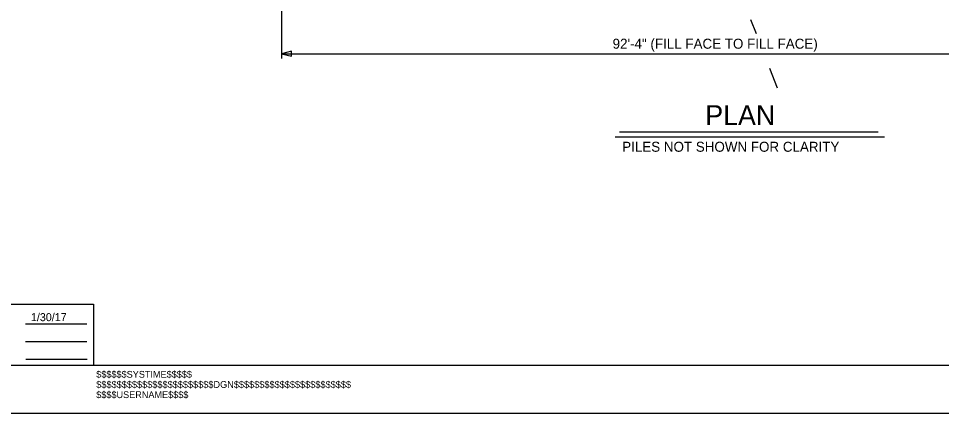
# Model space of a CAD drawing. Extents: x -20 to 509, y -659 to 21.
# Drawn here: x 47.1 to 139.4, y -176.3 to -136.8 of the extents above; entities that cross this region are included whole.
import ezdxf

# ---------------------------------------------------------------- set-up
doc = ezdxf.new("R2010")
doc.units = 0
for name, color, linetype in [('Auto Dimensioning', 7, 'Continuous'), ('Exist Hydro Stream or Body of Water', 7, 'Continuous'), ('Plan Sheet CELL', 7, 'Continuous'), ('Plot Label CELL', 7, 'Continuous'), ('Plot Shape CELL', 7, 'Continuous'), ('Sub End Bent Cap Lines CELL', 7, 'Continuous'), ('Subtitle Text', 7, 'Continuous'), ('Text', 7, 'Continuous'), ('Title Text', 7, 'Continuous')]:
    doc.layers.add(name, color=color, linetype=linetype)

# ---------------------------------------------------------------- blocks, each defined once
blk = doc.blocks.new('AH')
at = {"layer": 'Sub End Bent Cap Lines CELL'}
blk.add_lwpolyline([(0, 0), (-1.25, 0.31), (-1.25, -0.31)], close=True, dxfattribs=at)

msp = doc.modelspace()

# ---------------------------------------------------------------- linework, layer by layer
at = {"layer": 'Auto Dimensioning'}
for p, q in [((73.409, -111.741), (73.409, -140.762)), ((73.409, -140.297), (165.739, -140.297))]:
    msp.add_line(p, q, dxfattribs=at)
at = {"layer": 'Exist Hydro Stream or Body of Water'}
for points in [[(120.862, -138.306), (120.314, -136.891)], [(122.965, -143.739), (122.205, -141.776)]]:
    msp.add_lwpolyline(points, dxfattribs=at)
at = {"layer": 'Plan Sheet CELL'}
for p, q in [((8.432, -165.361), (54.624, -165.361)), ((54.624, -165.361), (54.624, -171.454)), ((47.853, -167.339), (53.972, -167.339)), ((47.853, -169.094), (53.972, -169.094)), ((8.432, -171.454), (264.435, -171.454)), ((47.896, -170.85), (54.016, -170.85)), ((47.896, -170.85), (54.016, -170.85))]:
    msp.add_line(p, q, dxfattribs=at)
at = {"layer": 'Plot Shape CELL'}
msp.add_lwpolyline([(0, -0.303), (264.505, -0.303), (264.505, -176.303), (0, -176.303)], close=True, dxfattribs=at)
at = {"layer": 'Title Text'}
for p, q in [((107.201, -148.108), (133.043, -148.108)), ((106.752, -148.608), (133.661, -148.608))]:
    msp.add_line(p, q, dxfattribs=at)

# ---------------------------------------------------------------- block references
at = {"layer": 'Auto Dimensioning', "xscale": 0.8, "yscale": 0.8000000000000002, "rotation": 180}
msp.add_blockref('AH', (73.409, -140.297), dxfattribs=at)

# ---------------------------------------------------------------- texts
at = {"layer": 'Plot Label CELL'}
for s, height, p in [('$$$$$$SYSTIME$$$$$', 0.68029, (54.916, -172.716)), ('$$$$$$$$$$$$$$$$$$$$$$$DGN$$$$$$$$$$$$$$$$$$$$$$$', 0.68446, (54.916, -173.736)), ('$$$$USERNAME$$$$', 0.68029, (54.916, -174.756))]:
    msp.add_text(s, height=height, dxfattribs=at).set_placement(p)
at = {"layer": 'Subtitle Text'}
msp.add_text('1/30/17', height=0.8, dxfattribs=at).set_placement((48.389, -167.056))
at = {"layer": 'Text'}
for s, p in [('92\'-4" (FILL FACE TO FILL FACE)', (106.501, -139.797)), ('PILES NOT SHOWN FOR CLARITY', (107.458, -150.108))]:
    msp.add_text(s, height=1, dxfattribs=at).set_placement(p)
at = {"layer": 'Title Text'}
msp.add_text('PLAN', height=2, dxfattribs=at).set_placement((115.76, -147.446))

doc.saveas('drawing.dxf')
